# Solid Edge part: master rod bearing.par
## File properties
Author: Robert a Rhodes jr
Template: Normal.par
Last saved by: CADCIM
Revision: 10
Application: Solid Edge
Accuracy: 0.99
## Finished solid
Body 1: solid body, 4 faces, 4 edges, 0 vertices.
  Faces by surface: cylinder 2, plane 2
  Edges by curve: circle 4
Bounding box of the edges (mm): 52.000 x 52.000 x 70.000, from (-26, -26, -70) to (26, 26, 0).
Cylindrical faces by radius (mm): R23 x1, R26 x1
Planar faces by outward normal: +z 1, -z 1
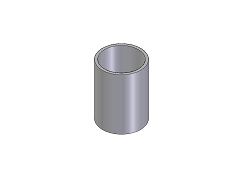
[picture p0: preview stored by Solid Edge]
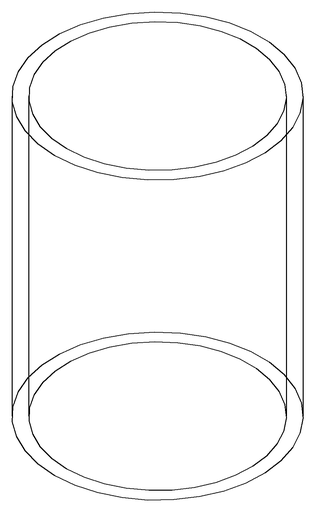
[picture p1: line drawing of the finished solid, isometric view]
